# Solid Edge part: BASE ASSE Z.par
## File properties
Subject: BASE ASSE Z
Author: f_grande
Template: Normal.par
Last saved by: f_grande
Revision: 9
Application: Solid Edge
Material: MDF
Stile della faccia: Marroncino
Coef. of Thermal Exp: 0.0
Thermal Conductivity: 0.0
Specific Heat: 0.0
Modulus of Elasticity: 0.0
Poisson's Ratio: 0.0
Yield Stress: 0.0
Ultimate Stress: 0.0
Elongation: 0.0
Tipo di contenuto documento: 0
Densità: 750,000 kg/m^3
Precisione: 0,990
Document Number: KR0124
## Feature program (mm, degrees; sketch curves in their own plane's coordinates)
sketch for "unnamed Protrusion 1" plane through (0, 0, 0) normal (0, -1, 0) x-axis (1, 0, 0)
  line (-32.0698, 29.0952) -> (96.9302, 29.0952)
  line (96.9302, 29.0952) -> (96.9302, -104.9048)
  line (96.9302, -104.9048) -> (-32.0698, -104.9048)
  line (-32.0698, -104.9048) -> (-32.0698, 29.0952)
  dimension (linear) = 32.0698
  dimension (linear) = 32.0698
extrude "unnamed Protrusion 1" add finite 19 along +normal
sketch for "Foro_1" plane through (32.4302, -19, -37.9048) normal (0, -1, 0) x-axis (1, 0, 0)
  hole centre (0, -38) bore radius 10
hole "Foro_1" diameter 20 through
sketch for "Foro_2" plane through (32.4302, -19, -37.9048) normal (0, -1, 0) x-axis (1, 0, 0)
  hole centre (41.5, -34) bore radius 6
hole "Foro_2" diameter 12 finite
sketch for "unnamed Hole 1" plane through (32.4302, -19, -37.9048) normal (0, -1, 0) x-axis (1, 0, 0)
  hole centre (-41.5, -34) bore radius 6
hole "unnamed Hole 1" finite
sketch for "Foro_4" plane through (32.4302, -19, -31.9048) normal (0, -1, 0) x-axis (1, 0, 0)
  hole centre (23.57, -20.43) bore radius 2.5
hole "Foro_4" diameter 5 through
sketch for "unnamed Hole 2" plane through (32.4302, -19, -31.9048) normal (0, -1, 0) x-axis (1, 0, 0)
  hole centre (23.57, -67.57) bore radius 2.5
hole "unnamed Hole 2" through
sketch for "unnamed Hole 3" plane through (32.4302, -19, -31.9048) normal (0, -1, 0) x-axis (1, 0, 0)
  hole centre (-23.57, -67.57) bore radius 2.5
hole "unnamed Hole 3" through
sketch for "unnamed Hole 4" plane through (32.4302, -19, -31.9048) normal (0, -1, 0) x-axis (1, 0, 0)
hole "unnamed Hole 4" through
pattern "unnamed Pattern 1" of "Foro_2", "unnamed Hole 1"
pattern "unnamed Pattern 2" of "Foro_4", "unnamed Hole 2", "unnamed Hole 3", "unnamed Hole 4"
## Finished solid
Body 1: solid body, 15 faces, 26 edges, 8 vertices.
  Faces by surface: plane 8, cylinder 7
  Edges by curve: circle 14, line 12
Bounding box of the edges (mm): 129.000 x 19.000 x 134.000, from (-32.0698, -19, -104.9048) to (96.9302, 0, 29.0952).
Cylindrical faces by radius (mm): R2.5 x4, R6 x2, R10 x1
Planar faces by outward normal: +x 1, +y 1, +z 1, -x 1, -y 3, -z 1
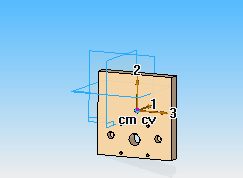
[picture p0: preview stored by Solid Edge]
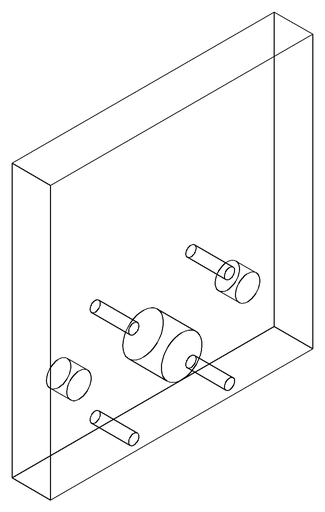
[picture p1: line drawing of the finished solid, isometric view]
